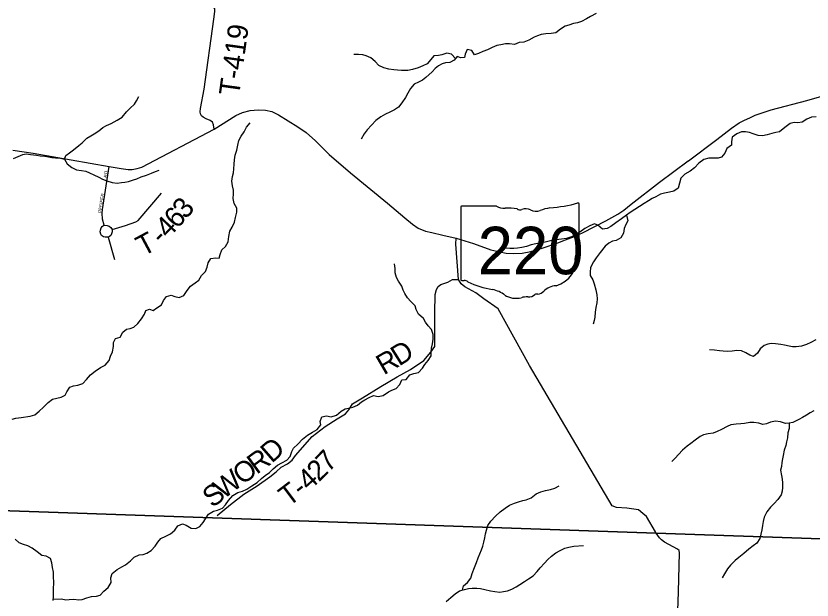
# Model space of a CAD drawing. Extents: x 1578669 to 1989827, y 208020 to 553079.
# Drawn here: x 1795443 to 1807123, y 394363 to 402929 of the extents above; entities that cross this region are included whole.
import ezdxf

# ---------------------------------------------------------------- set-up
doc = ezdxf.new("R2010")
doc.units = 0
for name, color, linetype in [('GM_X_County_Road', 7, 'Continuous'), ('GM_X_Minor_River', 7, 'Continuous'), ('GM_X_State_Location', 7, 'Continuous'), ('GM_X_State_Route', 7, 'Continuous'), ('GM_X_State_Shield', 7, 'Continuous'), ('GM_X_Township', 7, 'Continuous'), ('GM_X_Township_Road', 7, 'Continuous'), ('GM_X_Township_Road_Text', 7, 'Continuous'), ('GM_X_Township_Subdivision', 7, 'Continuous'), ('GM_X_Township_Subdivision_Text', 7, 'Continuous')]:
    doc.layers.add(name, color=color, linetype=linetype)

msp = doc.modelspace()

# ---------------------------------------------------------------- linework, layer by layer
at = {"layer": 'GM_X_County_Road'}
for points in [[(1804825, 395361), (1804692, 395586), (1804638, 395630), (1804574, 395685), (1804403, 395711), (1804255, 395721), (1804188, 395745), (1802978, 397802), (1802517, 398634), (1802308, 398782), (1802189, 398869), (1802027, 398956), (1801974, 399000), (1801934, 399066), (1801898, 399582), (1801901, 399668)], [(1805143, 393932), (1805162, 394484), (1805177, 395055), (1805173, 395090), (1805148, 395108), (1804958, 395213), (1804914, 395244), (1804885, 395276), (1804835, 395344), (1804825, 395361)]]:
    msp.add_lwpolyline(points, dxfattribs=at)
at = {"layer": 'GM_X_Minor_River'}
for points in [[(1803954, 402965), (1803872, 402920), (1803814, 402884), (1803740, 402845), (1803680, 402827), (1803624, 402817), (1803552, 402792), (1803500, 402778), (1803432, 402735), (1803363, 402679), (1803296, 402671), (1803218, 402664), (1803148, 402656), (1803096, 402639), (1803044, 402615), (1802968, 402571), (1802893, 402542), (1802824, 402540), (1802756, 402511), (1802684, 402521), (1802624, 402519), (1802556, 402504), (1802498, 402494), (1802428, 402468), (1802360, 402429), (1802292, 402405), (1802228, 402376), (1802172, 402360), (1802130, 402424), (1802064, 402436), (1802032, 402367), (1802026, 402317), (1801972, 402315), (1801918, 402333), (1801872, 402282), (1801810, 402244), (1801746, 402240), (1801696, 402225), (1801644, 402197), (1801592, 402159), (1801549, 402108), (1801457, 402028), (1801405, 401985), (1801347, 401959), (1801283, 401926), (1801229, 401862), (1801192, 401798), (1801160, 401733), (1801104, 401653), (1801054, 401593), (1800996, 401554), (1800926, 401516), (1800863, 401487), (1800797, 401451), (1800723, 401396), (1800657, 401326), (1800597, 401259), (1800553, 401199), (1800506, 401121)], [(1801893, 402305), (1801834, 402368), (1801764, 402384), (1801692, 402360), (1801642, 402349), (1801574, 402343), (1801530, 402289), (1801474, 402228), (1801412, 402198), (1801346, 402167), (1801260, 402141), (1801192, 402130), (1801100, 402126), (1801042, 402132), (1800988, 402137), (1800912, 402149), (1800839, 402167), (1800767, 402204), (1800713, 402262), (1800647, 402312), (1800582, 402344), (1800532, 402358), (1800468, 402365), (1800400, 402363)], [(1796154, 400830), (1796175, 400884), (1796227, 400922), (1796285, 400964), (1796365, 401027), (1796416, 401069), (1796484, 401136), (1796540, 401170), (1796592, 401201), (1796660, 401245), (1796720, 401293), (1796772, 401322), (1796840, 401350), (1796928, 401401), (1797001, 401445), (1797063, 401524), (1797117, 401574), (1797181, 401633), (1797211, 401683), (1797248, 401745)], [(1807183, 401450), (1807113, 401442), (1807045, 401414), (1806975, 401369), (1806915, 401363), (1806861, 401364), (1806803, 401350), (1806723, 401292), (1806646, 401231), (1806590, 401219), (1806534, 401204), (1806466, 401186), (1806396, 401170), (1806331, 401173), (1806257, 401201), (1806203, 401219), (1806147, 401228), (1806087, 401228), (1806021, 401202), (1805951, 401151), (1805939, 401083), (1805942, 401033), (1805874, 400986), (1805842, 400916), (1805794, 400856), (1805744, 400841), (1805692, 400843), (1805610, 400845), (1805534, 400824), (1805462, 400770), (1805400, 400703), (1805334, 400653), (1805258, 400610), (1805197, 400550), (1805179, 400474), (1805159, 400405), (1805097, 400357), (1805031, 400345), (1804959, 400332), (1804901, 400314), (1804829, 400275), (1804777, 400249), (1804722, 400215), (1804660, 400180), (1804592, 400136), (1804524, 400089), (1804454, 400047), (1804400, 400007), (1804326, 399952), (1804246, 399893), (1804172, 399839), (1804117, 399813), (1804048, 399800), (1803982, 399862), (1803932, 399878), (1803860, 399849)], [(1795389, 397015), (1795443, 397032), (1795519, 397042), (1795651, 397059), (1795719, 397077), (1795785, 397132), (1795847, 397190), (1795915, 397258), (1795981, 397307), (1796041, 397325), (1796105, 397338), (1796165, 397366), (1796189, 397416), (1796234, 397487), (1796286, 397503), (1796352, 397513), (1796422, 397540), (1796480, 397598), (1796538, 397667), (1796604, 397719), (1796684, 397774), (1796752, 397808), (1796809, 397874), (1796831, 397941), (1796859, 398005), (1796874, 398081), (1796874, 398141), (1796904, 398200), (1796970, 398218), (1797010, 398292), (1797066, 398335), (1797118, 398343), (1797170, 398365), (1797231, 398420), (1797287, 398488), (1797327, 398557), (1797347, 398607), (1797403, 398629), (1797455, 398607), (1797509, 398646), (1797579, 398692), (1797608, 398754), (1797650, 398815), (1797722, 398833), (1797774, 398813), (1797839, 398800), (1797907, 398830), (1797956, 398901), (1798006, 398967), (1798072, 399015), (1798126, 399056), (1798164, 399122), (1798223, 399179), (1798247, 399243), (1798263, 399309), (1798303, 399373), (1798373, 399380), (1798425, 399376), (1798441, 399430), (1798464, 399501), (1798516, 399549), (1798556, 399615), (1798567, 399695), (1798583, 399772), (1798613, 399830), (1798647, 399902), (1798666, 399975), (1798684, 400049), (1798682, 400111), (1798645, 400179), (1798629, 400251), (1798633, 400319), (1798633, 400375), (1798620, 400437), (1798612, 400504), (1798620, 400576), (1798633, 400628), (1798639, 400686), (1798643, 400756), (1798647, 400820), (1798660, 400885), (1798682, 400959), (1798700, 401035), (1798715, 401101), (1798747, 401164), (1798789, 401228), (1798825, 401296), (1798878, 401359)], [(1795406, 400836), (1795542, 400897), (1795592, 400905), (1795658, 400899), (1795744, 400888), (1795796, 400878), (1795869, 400870), (1795919, 400862), (1795971, 400853), (1796023, 400847), (1796095, 400841), (1796157, 400830), (1796193, 400762), (1796262, 400704), (1796332, 400674), (1796404, 400664), (1796466, 400651), (1796521, 400627), (1796587, 400597), (1796657, 400562), (1796713, 400536), (1796775, 400510), (1796854, 400486), (1796928, 400475), (1796990, 400485), (1797042, 400489), (1797096, 400502), (1797166, 400524), (1797216, 400538), (1797278, 400567), (1797358, 400595), (1797430, 400624), (1797492, 400648), (1797544, 400666)], [(1804399, 400006), (1804422, 399922), (1804389, 399870), (1804365, 399812), (1804357, 399744), (1804315, 399675), (1804251, 399637), (1804197, 399625), (1804142, 399594), (1804088, 399550), (1804012, 399459), (1803954, 399383), (1803918, 399321), (1803873, 399240), (1803865, 399170), (1803867, 399120), (1803906, 399060), (1803926, 399000), (1803952, 398910), (1803963, 398840), (1803969, 398778), (1803965, 398723), (1803952, 398653), (1803942, 398583), (1803934, 398513), (1803926, 398463), (1803913, 398407)], [(1803860, 399849), (1803790, 399813), (1803716, 399760), (1803658, 399724), (1803592, 399690), (1803520, 399667), (1803448, 399653), (1803322, 399638), (1803264, 399626), (1803208, 399611), (1803148, 399603), (1803072, 399587), (1803002, 399570), (1802934, 399546), (1802864, 399533), (1802800, 399523), (1802746, 399517), (1802690, 399517), (1802620, 399524)], [(1801566, 398258), (1801540, 398332), (1801489, 398384), (1801453, 398438), (1801421, 398492), (1801348, 398557), (1801316, 398623), (1801300, 398677), (1801235, 398741), (1801187, 398795), (1801147, 398857), (1801122, 398909), (1801102, 398965), (1801056, 399037), (1801028, 399091), (1801005, 399161), (1801005, 399227), (1800999, 399295)], [(1795992, 394378), (1796110, 394383), (1796176, 394366), (1796226, 394370), (1796292, 394374), (1796365, 394365), (1796415, 394369), (1796485, 394395), (1796553, 394416), (1796623, 394420), (1796677, 394434), (1796733, 394491), (1796798, 394545), (1796838, 394618), (1796836, 394690), (1796853, 394754), (1796927, 394810), (1796997, 394849), (1797051, 394879), (1797123, 394940), (1797177, 394990), (1797249, 395027), (1797309, 395033), (1797363, 395051), (1797429, 395090), (1797483, 395154), (1797526, 395214), (1797570, 395267), (1797644, 395301), (1797712, 395334), (1797776, 395388), (1797820, 395452), (1797888, 395483), (1797942, 395459), (1798014, 395415), (1798080, 395414), (1798140, 395440), (1798192, 395498), (1798226, 395553), (1798269, 395621), (1798339, 395664), (1798399, 395682), (1798471, 395708), (1798515, 395759), (1798559, 395823), (1798625, 395894), (1798697, 395942), (1798767, 395962), (1798829, 395991), (1798906, 396039), (1798980, 396086), (1799046, 396146), (1799098, 396187), (1799162, 396233), (1799216, 396287), (1799278, 396342), (1799344, 396376), (1799415, 396413), (1799465, 396469), (1799489, 396541), (1799517, 396592), (1799577, 396650), (1799648, 396721), (1799722, 396781), (1799792, 396824), (1799862, 396864), (1799914, 396930), (1799908, 396981), (1799929, 397049), (1800001, 397065), (1800067, 397050), (1800147, 397072), (1800213, 397132), (1800273, 397165), (1800323, 397177), (1800385, 397193), (1800453, 397220), (1800511, 397272), (1800563, 397297), (1800627, 397331), (1800689, 397363), (1800759, 397348), (1800829, 397362), (1800907, 397415), (1800959, 397441), (1801021, 397463), (1801077, 397524), (1801102, 397592), (1801170, 397598), (1801224, 397665), (1801280, 397683), (1801348, 397700), (1801408, 397762), (1801444, 397816), (1801490, 397875), (1801535, 397943), (1801533, 397993), (1801539, 398059), (1801553, 398122), (1801566, 398188), (1801566, 398258)], [(1807180, 398177), (1807106, 398139), (1807040, 398112), (1806970, 398088), (1806888, 398076), (1806838, 398077), (1806786, 398085), (1806718, 398099), (1806666, 398112), (1806584, 398122), (1806525, 398126), (1806473, 398117), (1806419, 398097), (1806360, 398049), (1806322, 397984), (1806264, 397936), (1806212, 397956), (1806152, 397987), (1806087, 398019), (1806017, 398021), (1805951, 398012), (1805883, 398010), (1805819, 398012), (1805763, 398017), (1805691, 398027), (1805619, 398033)], [(1807149, 397137), (1807097, 397107), (1807041, 397074), (1806983, 397042), (1806929, 397013), (1806839, 396969), (1806787, 396955), (1806735, 396952), (1806659, 396976), (1806585, 396986), (1806515, 396973), (1806453, 396947), (1806401, 396936), (1806340, 396956), (1806268, 396968), (1806208, 396966), (1806130, 396951), (1806076, 396947), (1806008, 396944), (1805930, 396930), (1805876, 396910), (1805792, 396865), (1805732, 396833), (1805674, 396812), (1805596, 396800), (1805532, 396784), (1805480, 396761), (1805406, 396709), (1805342, 396658), (1805291, 396620), (1805221, 396559), (1805161, 396497), (1805115, 396445), (1805065, 396394)], [(1806787, 396955), (1806789, 396878), (1806768, 396814), (1806760, 396740), (1806748, 396684), (1806737, 396630), (1806715, 396563), (1806697, 396485), (1806687, 396433), (1806680, 396379), (1806672, 396323), (1806662, 396268), (1806676, 396188), (1806683, 396134), (1806687, 396080), (1806689, 396012), (1806685, 395960), (1806668, 395904), (1806622, 395837), (1806566, 395781), (1806514, 395727), (1806461, 395658), (1806419, 395576), (1806407, 395516), (1806397, 395455), (1806386, 395391), (1806354, 395267), (1806312, 395198), (1806259, 395156), (1806197, 395110), (1806123, 395047), (1806049, 394989), (1805995, 394942), (1805925, 394874), (1805880, 394819), (1805836, 394747), (1805804, 394689)], [(1801993, 394511), (1802009, 394570), (1802069, 394619), (1802115, 394683), (1802135, 394751), (1802168, 394842), (1802198, 394912), (1802222, 394980), (1802248, 395041), (1802271, 395099), (1802291, 395155), (1802305, 395213), (1802321, 395276), (1802334, 395334), (1802346, 395388), (1802366, 395454), (1802410, 395522), (1802477, 395595), (1802549, 395658), (1802619, 395708), (1802685, 395754), (1802755, 395783), (1802815, 395803), (1802877, 395822), (1802927, 395834), (1803001, 395862), (1803073, 395919), (1803145, 395951), (1803213, 395970), (1803283, 395984), (1803351, 396002), (1803411, 396037)], [(1795990, 394355), (1795994, 394413), (1795996, 394465), (1795995, 394539), (1795997, 394607), (1795996, 394721), (1795994, 394772), (1795980, 394840), (1795968, 394908), (1795949, 394974), (1795885, 395005), (1795823, 395015), (1795753, 395071), (1795682, 395123), (1795618, 395156), (1795556, 395178), (1795488, 395204), (1795431, 395254)], [(1802324, 394520), (1802406, 394500), (1802468, 394487), (1802540, 394481), (1802597, 394487), (1802653, 394500), (1802717, 394524), (1802782, 394556), (1802836, 394593), (1802902, 394635), (1802964, 394674), (1803030, 394718), (1803092, 394783), (1803132, 394833), (1803197, 394903), (1803247, 394958), (1803299, 395008), (1803365, 395053), (1803427, 395091), (1803497, 395123), (1803553, 395138), (1803627, 395152), (1803767, 395161)], [(1801754, 394343), (1801824, 394399), (1801888, 394452), (1801950, 394498), (1802022, 394520), (1802082, 394533), (1802134, 394539), (1802204, 394535), (1802256, 394534), (1802324, 394520)]]:
    msp.add_lwpolyline(points, dxfattribs=at)
at = {"layer": 'GM_X_State_Route'}
for points in [[(1805311, 400805), (1805727, 401115), (1805941, 401281), (1806051, 401359), (1806131, 401398), (1806208, 401435), (1806290, 401473), (1806392, 401510), (1806522, 401553), (1807048, 401689), (1807336, 401770)], [(1795396, 400962), (1795695, 400914), (1796811, 400722), (1796985, 400692), (1797090, 400678), (1797148, 400679), (1797222, 400692), (1797291, 400712), (1798353, 401269), (1798671, 401467), (1798767, 401511), (1798880, 401540), (1798996, 401550), (1799103, 401547), (1799196, 401526), (1799295, 401479), (1799579, 401302), (1799700, 401221), (1799836, 401096), (1800040, 400899), (1800350, 400626), (1800896, 400181), (1801148, 399966), (1801263, 399876), (1801342, 399818), (1801450, 399774), (1801542, 399752), (1801707, 399713), (1801901, 399668), (1802157, 399591), (1802412, 399498), (1802542, 399467), (1802636, 399450), (1802740, 399446), (1802870, 399452), (1802997, 399476), (1803163, 399525), (1803392, 399601), (1803506, 399643), (1803639, 399694), (1803766, 399755), (1804095, 399924), (1804274, 400023), (1804361, 400080), (1804467, 400166), (1804885, 400489), (1805307, 400802), (1805311, 400805)]]:
    msp.add_lwpolyline(points, dxfattribs=at)
at = {"layer": 'GM_X_State_Shield'}
for p, q in [((1803708, 399614), (1803708, 400167)), ((1801968, 400123), (1801968, 399066)), ((1802495, 400141), (1801985, 400141)), ((1803708, 399615), (1803708, 399614))]:
    msp.add_line(p, q, dxfattribs=at)
for centre, major_axis, start_param, end_param in [((1803089, 401582), (1845, 0), 4.814394, 5.042369), ((1803689, 400170), (19.4, 0), 6.141152, 7.989035), ((1801988, 400125), (20.2, 0), 1.712693, 3.28349), ((1802616, 400264), (196, 0), 4.042523, 4.731795), ((1802681, 399548), (702, 0), 1.404758, 1.657858), ((1802841, 400131), (56.4, 0), 3.836095, 5.185415), ((1802923, 400008), (117, 0), 0.950623, 2.079405), ((1803075, 400176), (141, 0), 4.081561, 5.145723), ((1803324, 399818), (371, 0), 1.699011, 2.107814), ((1803704, 399574), (30, 0), 1.883978, 3.671073), ((1803688, 399612), (20.7, 0), 5.05454, 6.418171), ((1803513, 399504), (180, 0), 5.934695, 6.695948), ((1803192, 399313), (462, 0), 5.101752, 6.440018), ((1803778, 399383), (131, 0), 2.387724, 3.262537), ((1801988, 399064), (20.3, 0), 3.00124, 4.508301), ((1801991, 399172), (155, 0), 4.665946, 4.897461), ((1802023, 399005), (56, 0), 0.519207, 1.627899), ((1802730, 399955), (1333, 0), 4.195997, 4.488961), ((1802332, 398592), (417, 0), 0.823519, 1.323587), ((1803066, 398964), (149, 0), 4.937069, 5.64225), ((1803387, 398770), (253, 0), 1.647645, 2.488434), ((1802783, 399000), (265, 0), 4.026481, 4.996735), ((1802936, 398635), (217, 0), 1.495662, 1.94098), ((1802956, 398921), (141, 0), 4.691044, 5.507374), ((1803083, 398819), (39.7, 0), 1.147584, 2.315152)]:
    msp.add_ellipse(centre, major_axis=major_axis, ratio=0.8, start_param=start_param, end_param=end_param, dxfattribs=at)
at = {"layer": 'GM_X_Township'}
for points in [[(1794614, 432491), (1800878, 431987), (1805343, 431619), (1806251, 431556), (1812296, 431154), (1812748, 423763), (1812981, 420551), (1813183, 417646), (1813169, 417495), (1813101, 417318), (1811396, 411352), (1811003, 410233), (1810653, 409191), (1809037, 404233), (1808867, 403681), (1808758, 403152), (1808680, 402775), (1808603, 402344), (1807250, 395261), (1804835, 395344), (1793085, 395748)], [(1793085, 395748), (1804835, 395344), (1807250, 395261), (1817353, 395143), (1817268, 394775), (1817084, 393899)]]:
    msp.add_lwpolyline(points, dxfattribs=at)
at = {"layer": 'GM_X_Township_Road'}
for points in [[(1798353, 401269), (1798342, 401333), (1798327, 401371), (1798293, 401397), (1798232, 401420), (1798189, 401444), (1798166, 401463), (1798150, 401492), (1798144, 401524), (1798151, 401570), (1798205, 401855), (1798346, 402882), (1798363, 402993), (1798363, 403034), (1798346, 403059), (1798345, 403059)], [(1796857, 399798), (1797048, 399854), (1797204, 399911), (1797237, 399931), (1797580, 400328)], [(1796794, 399683), (1796889, 399355)], [(1798393, 395604), (1798592, 395762), (1798787, 395916), (1798982, 396037), (1799167, 396169), (1799260, 396245), (1799336, 396311), (1799426, 396360), (1799497, 396414), (1799543, 396482), (1799790, 396761), (1799981, 396909), (1800156, 397021), (1800276, 397094), (1800327, 397152), (1800381, 397242), (1800526, 397328), (1800797, 397493), (1801034, 397635), (1801233, 397745), (1801426, 397876), (1801528, 397998), (1801587, 398080), (1801587, 398574), (1801594, 398844), (1801614, 398919), (1801637, 398960), (1801675, 398991), (1801777, 399026), (1801846, 399064), (1801934, 399066)]]:
    msp.add_lwpolyline(points, dxfattribs=at)
at = {"layer": 'GM_X_Township_Subdivision'}
for points in [[(1796737, 399860), (1796712, 399950), (1796708, 400034), (1796715, 400092), (1796811, 400722)], [(1796737, 399860), (1796781, 399856), (1796810, 399846), (1796837, 399826), (1796857, 399798), (1796857, 399763), (1796846, 399731), (1796834, 399711), (1796816, 399695), (1796794, 399683), (1796754, 399682), (1796725, 399688), (1796700, 399711), (1796687, 399730), (1796679, 399761), (1796682, 399789), (1796691, 399819), (1796708, 399840), (1796730, 399860)]]:
    msp.add_lwpolyline(points, dxfattribs=at)

# ---------------------------------------------------------------- texts
at = {"layer": 'GM_X_State_Location'}
for s in ['s', 'r']:
    msp.add_text(s, height=1, dxfattribs=at).set_placement((1802819, 399524))
msp.add_text('220', height=1, rotation=0, dxfattribs=at).set_placement((1802466, 399452))
at = {"layer": 'GM_X_State_Shield'}
msp.add_text('220', height=696.1, dxfattribs=at).set_placement((1802217, 399141))
at = {"layer": 'GM_X_Township_Road_Text'}
for s, rotation, p in [('T-419', 82.0983, (1798716, 401747)), ('3', 48.9182, (1797934, 399937)), ('6', 48.3281, (1797809, 399796)), ('4', 46.4389, (1797674, 399654)), ('T', 28.1388, (1797308, 399397)), ('-', 45.7921, (1797586, 399563)), ('D', 32.074, (1801063, 397785)), ('R', 30.1719, (1800840, 397656)), ('D', 41.116, (1799195, 396360)), ('R', 36.1151, (1798974, 396197)), ('7', 46.4829, (1800028, 396225)), ('O', 36.0488, (1798760, 396041)), ('2', 44.3216, (1799887, 396087)), ('W', 37.5134, (1798486, 395831)), ('4', 41.9193, (1799739, 395954)), ('T', 36.9796, (1799442, 395724)), ('S', 38.0958, (1798327, 395706)), ('-', 38.6878, (1799629, 395865))]:
    msp.add_text(s, height=300, rotation=rotation, dxfattribs=at).set_placement(p)
at = {"layer": 'GM_X_Township_Subdivision_Text'}
for s, rotation, p in [('RD', 83.9946, (1796781, 400555)), ('PFEIFER', 80.7103, (1796697, 400036))]:
    msp.add_text(s, height=50, rotation=rotation, dxfattribs=at).set_placement(p)

doc.saveas('drawing.dxf')
